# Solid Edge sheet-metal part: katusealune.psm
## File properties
Author: Administrator
Template: Normal.psm
Last saved by: Administrator
Revision: 2
Application: Solid Edge
Accuracy: 0,990
Material Thickness: 1,00 mm
Bend Radius: 1,00 mm
Relief Width: 1,00 mm
Relief Length: 0,00 mm
Neutral Factor: 0,330
Minimum Arc Length: 0,10 mm
Deviational Tolerance: 0,10 mm
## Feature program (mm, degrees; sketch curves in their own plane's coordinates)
base tab "unnamed BaseTab 1"
jog tab "JogTab_3"  OffsetDistance = 10 mm
flange "Flange_2"
louver "Louver_2"  LouverDepth = 5 mm; LouverHeight = 2 mm
dimple "Dimple_1"
bead "unnamed Bead 1"
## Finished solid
Body 1: solid body, 62 faces, 150 edges, 94 vertices.
  Faces by surface: plane 30, cylinder 20, cone 4, sphere 4, torus 4
  Edges by curve: line 96, circle 46, ellipse 8
Bounding box of the edges (mm; curved faces can reach further): 45.000 x 75.000 x 18.250, from (-22.5, -37.5, -12.5) to (22.5, 37.5, 5.75).
Cylindrical faces by radius (mm): R1 x15, R2 x3, R6.25 x1, R7.25 x1
Conical faces (half-angle, radius in mm at the cone's reference point): 15 deg R0.3014 x1, 15 deg R0.6363 x1, 15 deg R1.2673 x1, 15 deg R1.6023 x1
Toroidal faces (ring radius, tube radius in mm): R0.5 r1 x2, R1.6023 r1 x2
Spherical faces by radius (mm): R6.25 x2, R7.25 x2
Planar faces by outward normal: +x 4, +y 3, +z 5, -x 5, -y 3, -z 6, oblique 4
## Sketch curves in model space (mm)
line (22.5, 37.5, 0) -> (22.5, -37.5, 0)
line (22.5, -37.5, 0) -> (-22.5, -37.5, 0)
line (-22.5, -37.5, 0) -> (-22.5, 37.5, 0)
line (-22.5, 37.5, 0) -> (22.5, 37.5, 0)
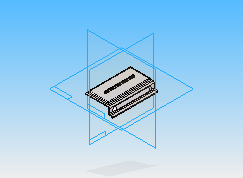
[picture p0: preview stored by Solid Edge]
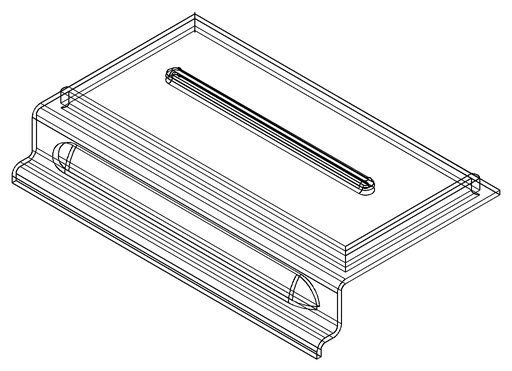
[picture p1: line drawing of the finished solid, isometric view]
